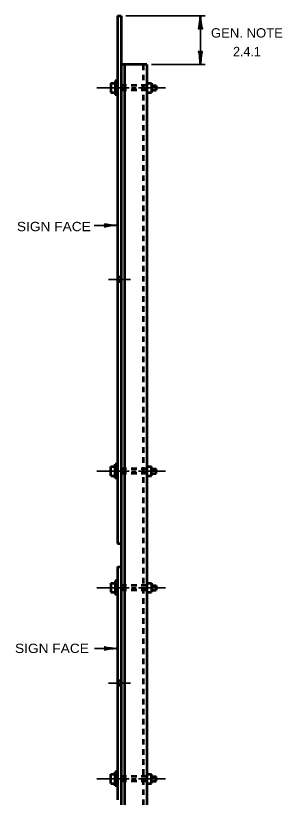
# Model space of a CAD drawing. Extents: x -87 to 768, y -466 to 78.
# Drawn here: x 149.4 to 218.1, y -262.3 to -61 of the extents above; entities that cross this region are included whole.
import ezdxf
from ezdxf.enums import TextEntityAlignment as Align

# ---------------------------------------------------------------- set-up
doc = ezdxf.new("R2010")
doc.units = 0
doc.header["$LTSCALE"] = 0.96
doc.linetypes.add('SHORT_DASHED', pattern=[2.7, 1.5, -1.2])
doc.layers.add('1', color=7, linetype='Continuous', lineweight=53)

msp = doc.modelspace()

# ---------------------------------------------------------------- linework, layer by layer
at = {"layer": '1'}
for p, q in [((175.7102, -61.0329), (175.7102, -196.9179)), ((175.7102, -61.0329), (176.6102, -61.0329)), ((176.6102, -61.0329), (176.6102, -297.7179)), ((183.2102, -73.6329), (176.6102, -73.6329)), ((177.5102, -73.6329), (177.5102, -297.7179)), ((183.2102, -73.6329), (183.2102, -297.7179)), ((173.9102, -78.4329), (173.9102, -80.8329)), ((173.9102, -78.4329), (175.1102, -78.4329)), ((175.7102, -77.8329), (175.1102, -77.8329)), ((175.1102, -77.8329), (175.1102, -81.4329)), ((183.2102, -78.4329), (184.4102, -78.4329)), ((184.4102, -78.4329), (184.4102, -80.8329)), ((184.4102, -79.0329), (185.6102, -79.0329)), ((184.4102, -80.2329), (185.6102, -80.2329)), ((185.6102, -79.0329), (185.6102, -80.2329)), ((173.9102, -80.8329), (175.1102, -80.8329)), ((175.7102, -81.4329), (175.1102, -81.4329)), ((183.2102, -80.8329), (184.4102, -80.8329)), ((176.6102, -128.3754), (175.7102, -128.3754)), ((176.6102, -129.5754), (175.7102, -129.5754)), ((173.9102, -179.5179), (173.9102, -177.1179)), ((173.9102, -177.1179), (175.1102, -177.1179)), ((175.7102, -176.5179), (175.1102, -176.5179)), ((175.1102, -180.1179), (175.1102, -176.5179)), ((183.2102, -177.1179), (184.4102, -177.1179)), ((184.4102, -179.5179), (184.4102, -177.1179)), ((184.4102, -177.7179), (185.6102, -177.7179)), ((184.4102, -178.9179), (185.6102, -178.9179)), ((185.6102, -178.9179), (185.6102, -177.7179)), ((173.9102, -179.5179), (175.1102, -179.5179)), ((175.7102, -180.1179), (175.1102, -180.1179)), ((183.2102, -179.5179), (184.4102, -179.5179)), ((175.7102, -196.9179), (176.6102, -196.9179)), ((175.7102, -202.9179), (176.6102, -202.9179)), ((175.7102, -202.9179), (175.7102, -262.9179)), ((173.9102, -207.1179), (173.9102, -209.5179)), ((173.9102, -207.1179), (175.1102, -207.1179)), ((175.7102, -206.5179), (175.1102, -206.5179)), ((175.1102, -206.5179), (175.1102, -210.1179)), ((183.2102, -207.1179), (184.4102, -207.1179)), ((184.4102, -207.1179), (184.4102, -209.5179)), ((184.4102, -207.7179), (185.6102, -207.7179)), ((184.4102, -208.9179), (185.6102, -208.9179)), ((185.6102, -207.7179), (185.6102, -208.9179)), ((173.9102, -209.5179), (175.1102, -209.5179)), ((175.7102, -210.1179), (175.1102, -210.1179)), ((183.2102, -209.5179), (184.4102, -209.5179)), ((176.6102, -232.318), (175.7102, -232.318)), ((176.6102, -233.518), (175.7102, -233.518)), ((173.9102, -258.7181), (173.9102, -256.3181)), ((173.9102, -256.3181), (175.1102, -256.3181)), ((175.7102, -255.7181), (175.1102, -255.7181)), ((175.1102, -259.3181), (175.1102, -255.7181)), ((183.2102, -256.3181), (184.4102, -256.3181)), ((184.4102, -258.7181), (184.4102, -256.3181)), ((184.4102, -256.9181), (185.6102, -256.9181)), ((185.6102, -258.1181), (185.6102, -256.9181)), ((173.9102, -258.7181), (175.1102, -258.7181)), ((175.7102, -259.3181), (175.1102, -259.3181)), ((183.2102, -258.7181), (184.4102, -258.7181)), ((184.4102, -258.1181), (185.6102, -258.1181))]:
    msp.add_line(p, q, dxfattribs=at)
at = {"layer": '1', "lineweight": 35}
for p, q in [((177.8102, -61.0329), (198.2102, -61.0329)), ((197.0102, -61.0329), (197.0102, -73.6329)), ((184.4102, -73.6329), (198.2102, -73.6329)), ((178.7102, -79.6329), (170.3102, -79.6329)), ((180.5102, -79.6329), (179.3102, -79.6329)), ((188.0102, -79.6329), (181.1102, -79.6329)), ((175.6766, -115.0375), (169.6766, -115.0375)), ((179.0102, -128.9754), (173.3102, -128.9754)), ((178.7102, -178.3179), (170.3102, -178.3179)), ((180.5102, -178.3179), (179.3102, -178.3179)), ((188.0102, -178.3179), (181.1102, -178.3179)), ((178.7102, -208.3179), (170.3102, -208.3179)), ((180.5102, -208.3179), (179.3102, -208.3179)), ((188.0102, -208.3179), (181.1102, -208.3179)), ((175.7306, -223.9756), (169.7306, -223.9756)), ((179.0102, -232.918), (173.3102, -232.918)), ((178.7102, -257.5181), (170.3102, -257.5181)), ((180.5102, -257.5181), (179.3102, -257.5181)), ((188.0102, -257.5181), (181.1102, -257.5181))]:
    msp.add_line(p, q, dxfattribs=at)
at = {"layer": '1', "linetype": 'SHORT_DASHED'}
for p, q in [((182.3102, -73.6329), (182.3102, -297.7179)), ((183.2102, -79.0329), (175.7102, -79.0329)), ((183.2102, -80.2329), (175.7102, -80.2329)), ((183.2102, -177.7179), (175.7102, -177.7179)), ((183.2102, -178.9179), (175.7102, -178.9179)), ((183.2102, -207.7179), (175.7102, -207.7179)), ((183.2102, -208.9179), (175.7102, -208.9179)), ((183.2102, -256.9181), (175.7102, -256.9181)), ((183.2102, -258.1181), (175.7102, -258.1181))]:
    msp.add_line(p, q, dxfattribs=at)
at = {"layer": '1', "lineweight": 40}
for centre, major_axis, ratio, start_param, end_param in [((196.7563, -62.3775), (0.2108, 2.1077), 0.07063, 3.14071475, 5.41810995), ((196.7563, -62.3775), (0.2108, 2.1077), 0.07063, 3.14071475, 5.41810995), ((197.3418, -62.3423), (-0.1874, 2.1428), 0.122415, 0.89635335, 3.14159265), ((197.3418, -62.3423), (-0.1874, 2.1428), 0.122415, 0.89635335, 3.14159265), ((196.6786, -72.3235), (0.1874, -2.1428), 0.122415, 0.89635335, 3.14159265), ((197.2641, -72.2883), (-0.2108, -2.1077), 0.07063, 3.14071475, 5.41810995), ((174.332, -114.7836), (2.1077, -0.2108), 0.07063, 3.14071475, 5.41810995), ((174.3672, -115.3691), (2.1428, 0.1874), 0.122415, 0.89635335, 3.14159265), ((174.4212, -224.3072), (2.1428, 0.1874), 0.122415, 0.89635335, 3.14159265), ((174.386, -223.7217), (2.1077, -0.2108), 0.07063, 3.14071475, 5.41810995)]:
    msp.add_ellipse(centre, major_axis=major_axis, ratio=ratio, start_param=start_param, end_param=end_param, dxfattribs=at)

# ---------------------------------------------------------------- texts
at = {"layer": '1'}
for s, width, p in [('GEN. NOTE', 1.05, (209.0012, -66.6633)), ('SIGN FACE', 1.1, (159.2802, -116.5252)), ('SIGN FACE', 1.1, (158.7912, -225.1405))]:
    msp.add_text(s, height=2.4, dxfattribs=dict(at, width=width)).set_placement(p, align=Align.CENTER)
msp.add_text('2.4.1', height=2.4, dxfattribs=at).set_placement((209.0012, -71.4633), align=Align.CENTER)

doc.saveas('drawing.dxf')
